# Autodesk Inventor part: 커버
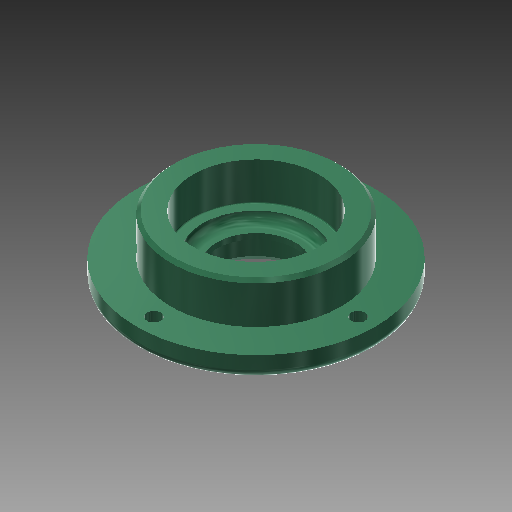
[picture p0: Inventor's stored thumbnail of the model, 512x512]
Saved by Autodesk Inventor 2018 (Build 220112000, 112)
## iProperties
Company: 한국ATC센터
Created: 2016-04
Part Number: 커버
Document SubType Name: Modeling
Designer: mdu
Density: 7.86 g/cm^3
Mass: 351.567 g
Surface Area: 161.165 cm^2
Volume: 44.7286 cm^3
Material: 강철, 연강
Appearance: 강철
Author: mdu
Revision Number: 1
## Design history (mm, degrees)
sketch "스케치1"
  geometry: C1 r 38 at (0, 0); 1 further point
  constraints: 1 centre point, 1 coincident
  dimensions: "d0" = 76 diameter of C1
extrude "돌출1" new body sketch "스케치1" distance "d1" = 7; taper "d2" = 0 deg
sketch "스케치2"
  geometry: C1 r 27 at (0, 0); 1 further point
  constraints: 1 centre point, 1 coincident
  dimensions: "d3" = 54 diameter of C1
extrude "돌출2" join sketch "스케치2" distance "d4" = 13; taper "d5" = 0 deg
sketch "스케치3"
  geometry: C1 r 20 at (0, 0); 1 further point
  constraints: 1 centre point, 1 coincident
  dimensions: "d6" = 40 diameter of C1
extrude "돌출3" join sketch "스케치3" distance "d7" = 5; taper "d8" = 0 deg
hole "구멍1" diameter "d11" = 25; stored, may be unused: countersink angle "d15" = 90 deg, drill point angle "d17" = 118 deg; dims "d9" = 10, "d10" = 10, "d12" = 6, "d13" = 32, "d14" = 8.3, "d16" = 8
hole "구멍2" diameter "d20" = 34; stored, may be unused: countersink angle "d24" = 90 deg, drill point angle "d26" = 0 deg; dims "d18" = 10, "d19" = 10, "d21" = 6, "d22" = 40, "d23" = 12, "d25" = 3
fillet "모깎기2" dims "d34" = 3
fillet "모깎기1" dims "d27" = 0.3
chamfer "모따기1" distance "d28" = 1; stored, may be unused: second distance "d29" = 2, angle "d30" = 45 deg
chamfer "모따기2" distance "d31" = 1.2; stored, may be unused: second distance "d32" = 2, angle "d33" = 30 deg
sketch "스케치4" dims "d35" = 65
  geometry: 3 further points
  constraints: 2 horizontal alignment, 1 coincident, 2 other
hole "구멍3" sketch "스케치4" at (32.5, 0) diameter "d36" = 4.5; stored, may be unused: countersink angle "d40" = 90 deg, drill point angle "d42" = 118 deg; dims "d37" = 6, "d38" = 8, "d39" = 4.4, "d41" = 13
node "솔리드1"
pattern_circular "원형 패턴1" dims angle "d44" = 360 deg
